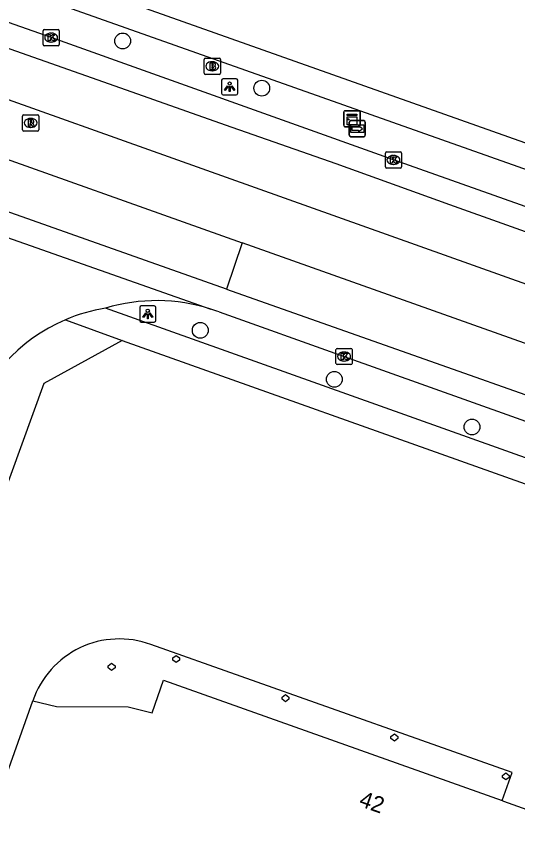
# Model space of a CAD drawing. Extents: x 155018 to 156648, y 383980 to 385733.
# Drawn here: x 155544.9 to 155575.9, y 385170.3 to 385221.4 of the extents above; entities that cross this region are included whole.
import ezdxf

# ---------------------------------------------------------------- set-up
doc = ezdxf.new("R2010")
doc.units = 0
for name, color, linetype in [('IMGEO_Boom', 7, 'Continuous'), ('IMGEO_Brandkraan', 7, 'Continuous'), ('IMGEO_Kast', 7, 'Continuous'), ('IMGEO_Kolk', 7, 'Continuous'), ('IMGEO_Lichtpunt', 7, 'Continuous'), ('IMGEO_OVBaan_gesloten', 7, 'Continuous'), ('IMGEO_Pand', 7, 'Continuous'), ('IMGEO_Pand_nummerreeks', 7, 'Continuous'), ('IMGEO_Pand_overbouw', 7, 'Continuous'), ('IMGEO_Rijbaan_lokaal_gesloten', 7, 'Continuous'), ('IMGEO_Rioolput', 7, 'Continuous'), ('IMGEO_Voetpad_open', 7, 'Continuous'), ('IMGEO_Wegwijzer', 7, 'Continuous')]:
    doc.layers.add(name, color=color, linetype=linetype)

msp = doc.modelspace()

# ---------------------------------------------------------------- linework, layer by layer
at = {"layer": 'IMGEO_Boom'}
for centre in [(155551.473, 385219.923), (155560.071, 385217.001), (155556.269, 385202.025), (155564.56, 385198.995), (155573.068, 385196.044)]:
    msp.add_circle(centre, 0.489, dxfattribs=at)
at = {"layer": 'IMGEO_Brandkraan'}
for p, q in [((155556.512, 385217.93), (155556.512, 385218.782)), ((155556.587, 385218.856), (155557.439, 385218.856)), ((155557.513, 385218.782), (155557.513, 385217.93)), ((155557, 385218.636), (155557.025, 385218.636)), ((155557.439, 385217.856), (155556.587, 385217.856)), ((155557.023, 385218.076), (155556.998, 385218.076))]:
    msp.add_line(p, q, dxfattribs=at)
for points in [[(155556.512, 385217.93), (155556.512, 385218.782)], [(155556.587, 385218.856), (155557.439, 385218.856)], [(155557.513, 385218.782), (155557.513, 385217.93)], [(155556.86, 385218.556), (155556.86, 385218.156), (155557.073, 385218.156)], [(155557.091, 385218.556), (155556.86, 385218.556)], [(155557.039, 385218.475), (155556.985, 385218.475), (155556.985, 385218.399)], [(155556.985, 385218.399), (155557.038, 385218.399)], [(155557.047, 385218.323), (155556.985, 385218.323), (155556.985, 385218.242)], [(155556.985, 385218.242), (155557.047, 385218.242)], [(155557.439, 385217.856), (155556.587, 385217.856)]]:
    msp.add_lwpolyline(points, dxfattribs=at)
for centre, radius, start, end in [((155556.589, 385218.78), 0.0765, 91.552, 178.448), ((155556.589, 385218.78), 0.0765, 91.552, 178.448), ((155557.437, 385218.78), 0.0765, 1.552, 88.448), ((155557.437, 385218.78), 0.0765, 1.552, 88.448), ((155557.04, 385218.437), 0.0379, 267.8285, 90.9355), ((155557.048, 385218.282), 0.0404, 269.8759, 90.5077), ((155557.095, 385218.411), 0.145, 59.4692, 91.5367), ((155557.12, 385218.458), 0.0922, 285.5137, 58.1501), ((155557.125, 385218.266), 0.105, 301.3115, 78.989), ((155556.589, 385217.932), 0.0765, 181.552, 268.448), ((155556.589, 385217.932), 0.0765, 181.552, 268.448), ((155557.079, 385218.407), 0.251, 268.6676, 293.5347), ((155557.437, 385217.932), 0.0765, 271.552, 358.448), ((155557.437, 385217.932), 0.0765, 271.552, 358.448)]:
    msp.add_arc(centre, radius, start, end, dxfattribs=at)
for centre, major_axis, ratio, start_param, end_param in [((155556.999, 385218.356), (-0.387, 0.002), 0.722429, 4.712389, 7.853982), ((155557.024, 385218.356), (-0.39, 0.002), 0.717154, 1.570796, 4.712389)]:
    msp.add_ellipse(centre, major_axis=major_axis, ratio=ratio, start_param=start_param, end_param=end_param, dxfattribs=at)
at = {"layer": 'IMGEO_Kast'}
for p, q in [((155565.149, 385214.682), (155565.149, 385215.523)), ((155565.149, 385215.523), (155565.149, 385214.682)), ((155565.224, 385215.607), (155566.065, 385215.607)), ((155566.065, 385215.607), (155565.224, 385215.607)), ((155566.149, 385215.532), (155566.149, 385214.691)), ((155566.149, 385214.691), (155566.149, 385215.532)), ((155566.074, 385214.607), (155565.233, 385214.607)), ((155565.233, 385214.607), (155566.074, 385214.607))]:
    msp.add_line(p, q, dxfattribs=at)
for points in [[(155565.344, 385215.397), (155565.944, 385215.397), (155565.944, 385215.312), (155565.344, 385215.312), (155565.344, 385215.397)], [(155565.344, 385215.222), (155565.944, 385215.222), (155565.944, 385214.733), (155565.344, 385214.733), (155565.344, 385215.222)]]:
    msp.add_lwpolyline(points, dxfattribs=at)
msp.add_circle((155565.428, 385215.071), 0.0377, dxfattribs=at)
for centre, start, end in [((155565.227, 385215.529), 92.4484, 184.2845), ((155565.227, 385215.529), 92.4484, 184.2845), ((155566.071, 385215.529), 2.4484, 94.2845), ((155566.071, 385215.529), 2.4484, 94.2845), ((155565.227, 385214.685), 182.4484, 274.2845), ((155565.227, 385214.685), 182.4484, 274.2845), ((155566.071, 385214.685), 272.4484, 4.2845), ((155566.071, 385214.685), 272.4484, 4.2845)]:
    msp.add_arc(centre, 0.0779, start, end, dxfattribs=at)
at = {"layer": 'IMGEO_Kolk'}
for p, q in [((155546.551, 385219.702), (155546.551, 385220.554)), ((155546.626, 385220.628), (155547.478, 385220.628)), ((155547.039, 385220.408), (155547.064, 385220.408)), ((155547.552, 385220.554), (155547.552, 385219.702)), ((155547.062, 385219.848), (155547.037, 385219.848)), ((155547.478, 385219.628), (155546.626, 385219.628)), ((155567.713, 385212.135), (155567.713, 385212.987)), ((155567.788, 385213.061), (155568.64, 385213.061)), ((155568.201, 385212.841), (155568.226, 385212.841)), ((155568.714, 385212.987), (155568.714, 385212.135)), ((155568.224, 385212.281), (155568.199, 385212.281)), ((155568.64, 385212.061), (155567.788, 385212.061)), ((155564.661, 385199.976), (155564.661, 385200.828)), ((155564.736, 385200.902), (155565.588, 385200.902)), ((155565.662, 385200.828), (155565.662, 385199.976)), ((155565.149, 385200.682), (155565.174, 385200.682)), ((155565.588, 385199.902), (155564.736, 385199.902)), ((155565.172, 385200.122), (155565.147, 385200.122))]:
    msp.add_line(p, q, dxfattribs=at)
for points in [[(155546.551, 385219.702), (155546.551, 385220.554)], [(155546.626, 385220.628), (155547.478, 385220.628)], [(155546.872, 385220.328), (155546.995, 385220.328), (155546.995, 385220.177), (155547.125, 385220.328), (155547.289, 385220.328), (155547.143, 385220.177), (155547.296, 385219.928), (155547.144, 385219.928), (155547.059, 385220.092), (155546.995, 385220.025), (155546.995, 385219.928), (155546.872, 385219.928), (155546.872, 385220.328)], [(155547.552, 385220.554), (155547.552, 385219.702)], [(155547.478, 385219.628), (155546.626, 385219.628)], [(155567.713, 385212.135), (155567.713, 385212.987)], [(155567.788, 385213.061), (155568.64, 385213.061)], [(155568.034, 385212.761), (155568.157, 385212.761), (155568.157, 385212.61), (155568.287, 385212.761), (155568.451, 385212.761), (155568.305, 385212.61), (155568.458, 385212.361), (155568.306, 385212.361), (155568.221, 385212.525), (155568.157, 385212.458), (155568.157, 385212.361), (155568.034, 385212.361), (155568.034, 385212.761)], [(155568.714, 385212.987), (155568.714, 385212.135)], [(155568.64, 385212.061), (155567.788, 385212.061)], [(155564.661, 385199.976), (155564.661, 385200.828)], [(155564.736, 385200.902), (155565.588, 385200.902)], [(155565.662, 385200.828), (155565.662, 385199.976)], [(155564.982, 385200.602), (155565.105, 385200.602), (155565.105, 385200.451), (155565.235, 385200.602), (155565.399, 385200.602), (155565.253, 385200.451), (155565.406, 385200.202), (155565.254, 385200.202), (155565.169, 385200.366), (155565.105, 385200.299), (155565.105, 385200.202), (155564.982, 385200.202), (155564.982, 385200.602)], [(155565.588, 385199.902), (155564.736, 385199.902)]]:
    msp.add_lwpolyline(points, dxfattribs=at)
for centre, start, end in [((155546.628, 385220.552), 91.552, 178.448), ((155546.628, 385220.552), 91.552, 178.448), ((155547.476, 385220.552), 1.552, 88.448), ((155547.476, 385220.552), 1.552, 88.448), ((155546.628, 385219.704), 181.552, 268.448), ((155546.628, 385219.704), 181.552, 268.448), ((155547.476, 385219.704), 271.552, 358.448), ((155547.476, 385219.704), 271.552, 358.448), ((155567.79, 385212.985), 91.552, 178.448), ((155567.79, 385212.985), 91.552, 178.448), ((155568.638, 385212.985), 1.552, 88.448), ((155568.638, 385212.985), 1.552, 88.448), ((155567.79, 385212.137), 181.552, 268.448), ((155567.79, 385212.137), 181.552, 268.448), ((155568.638, 385212.137), 271.552, 358.448), ((155568.638, 385212.137), 271.552, 358.448), ((155564.738, 385200.826), 91.552, 178.448), ((155564.738, 385200.826), 91.552, 178.448), ((155565.586, 385200.826), 1.552, 88.448), ((155565.586, 385200.826), 1.552, 88.448), ((155564.738, 385199.978), 181.552, 268.448), ((155564.738, 385199.978), 181.552, 268.448), ((155565.586, 385199.978), 271.552, 358.448), ((155565.586, 385199.978), 271.552, 358.448)]:
    msp.add_arc(centre, 0.0765, start, end, dxfattribs=at)
for centre, major_axis, ratio, start_param, end_param in [((155547.038, 385220.128), (-0.387, 0.002), 0.722429, 4.712389, 7.853982), ((155547.063, 385220.128), (-0.39, 0.002), 0.717154, 1.570796, 4.712389), ((155568.2, 385212.561), (-0.387, 0.002), 0.722429, 4.712389, 7.853982), ((155568.225, 385212.561), (-0.39, 0.002), 0.717154, 1.570796, 4.712389), ((155565.148, 385200.402), (-0.387, 0.002), 0.722429, 4.712389, 7.853982), ((155565.173, 385200.402), (-0.39, 0.002), 0.717154, 1.570796, 4.712389)]:
    msp.add_ellipse(centre, major_axis=major_axis, ratio=ratio, start_param=start_param, end_param=end_param, dxfattribs=at)
at = {"layer": 'IMGEO_Lichtpunt'}
for p, q in [((155557.588, 385217.491), (155557.588, 385216.684)), ((155557.588, 385217.491), (155557.588, 385216.684)), ((155558.49, 385217.586), (155557.682, 385217.586)), ((155558.49, 385217.586), (155557.682, 385217.586)), ((155558.584, 385216.684), (155558.584, 385217.491)), ((155558.584, 385216.684), (155558.584, 385217.491)), ((155557.682, 385216.59), (155558.49, 385216.59)), ((155557.682, 385216.59), (155558.49, 385216.59)), ((155552.525, 385203.435), (155552.525, 385202.628)), ((155552.525, 385203.435), (155552.525, 385202.628)), ((155553.427, 385203.53), (155552.619, 385203.53)), ((155553.427, 385203.53), (155552.619, 385203.53)), ((155553.521, 385202.628), (155553.521, 385203.435)), ((155553.521, 385202.628), (155553.521, 385203.435)), ((155552.619, 385202.534), (155553.427, 385202.534)), ((155552.619, 385202.534), (155553.427, 385202.534))]:
    msp.add_line(p, q, dxfattribs=at)
for points in [[(155557.962, 385217.155), (155558.001, 385217.127), (155557.813, 385216.865), (155557.775, 385216.892), (155557.962, 385217.155)], [(155558.064, 385217.107), (155558.111, 385217.107), (155558.111, 385216.785), (155558.064, 385216.785), (155558.064, 385217.107)], [(155558.174, 385217.127), (155558.212, 385217.154), (155558.399, 385216.892), (155558.36, 385216.864), (155558.174, 385217.127)], [(155552.899, 385203.099), (155552.938, 385203.071), (155552.75, 385202.809), (155552.712, 385202.836), (155552.899, 385203.099)], [(155553.001, 385203.051), (155553.048, 385203.051), (155553.048, 385202.729), (155553.001, 385202.729), (155553.001, 385203.051)], [(155553.111, 385203.071), (155553.149, 385203.098), (155553.336, 385202.836), (155553.297, 385202.808), (155553.111, 385203.071)]]:
    msp.add_lwpolyline(points, dxfattribs=at)
for centre in [(155558.087, 385217.289), (155553.024, 385203.233)]:
    msp.add_circle(centre, 0.0994, dxfattribs=at)
for centre, start, end in [((155557.682, 385217.491), 90, 180), ((155557.682, 385217.491), 90, 180), ((155558.49, 385217.491), 0, 90), ((155558.49, 385217.491), 0, 90), ((155557.682, 385216.684), 180, 270), ((155557.682, 385216.684), 180, 270), ((155558.49, 385216.684), 270, 0), ((155558.49, 385216.684), 270, 360), ((155552.619, 385203.435), 90, 180), ((155552.619, 385203.435), 90, 180), ((155553.427, 385203.435), 0, 90), ((155553.427, 385203.435), 0, 90), ((155552.619, 385202.628), 180, 270), ((155552.619, 385202.628), 180, 270), ((155553.427, 385202.628), 270, 0), ((155553.427, 385202.628), 270, 360)]:
    msp.add_arc(centre, 0.0946, start, end, dxfattribs=at)
at = {"layer": 'IMGEO_OVBaan_gesloten'}
for points in [[(155513.143, 385227.411), (155532.678, 385220.473), (155596.803, 385197.629), (155623.968, 385187.963)], [(155511.979, 385224.068), (155531.528, 385217.123), (155540.881, 385213.823), (155558.855, 385207.433)], [(155622.855, 385184.672), (155594.693, 385194.693), (155558.855, 385207.433)]]:
    msp.add_lwpolyline(points, dxfattribs=at)
at = {"layer": 'IMGEO_Pand'}
for points in [[(155550.791, 385180.993), (155550.582, 385181.145), (155550.582, 385181.281), (155550.791, 385181.433), (155551, 385181.281), (155551, 385181.145), (155550.791, 385180.993)], [(155554.782, 385181.473), (155554.573, 385181.625), (155554.573, 385181.761), (155554.782, 385181.913), (155554.991, 385181.761), (155554.991, 385181.625), (155554.782, 385181.473)], [(155564.352, 385122.443), (155569.181, 385136.025), (155534.942, 385148.201), (155545.918, 385179.107), (155547.38, 385178.749), (155551.81, 385178.73), (155553.29, 385178.36), (155554, 385180.39), (155574.93, 385172.934), (155575.009, 385172.906), (155581.819, 385170.48), (155577.589, 385158.606), (155588.821, 385154.605), (155575.936, 385118.324), (155564.352, 385122.443)], [(155561.537, 385179.054), (155561.328, 385179.206), (155561.328, 385179.342), (155561.537, 385179.494), (155561.746, 385179.342), (155561.746, 385179.206), (155561.537, 385179.054)], [(155568.269, 385176.623), (155568.06, 385176.775), (155568.06, 385176.911), (155568.269, 385177.063), (155568.478, 385176.911), (155568.478, 385176.775), (155568.269, 385176.623)], [(155575.163, 385174.212), (155574.954, 385174.364), (155574.954, 385174.5), (155575.163, 385174.652), (155575.372, 385174.5), (155575.372, 385174.364), (155575.163, 385174.212)]]:
    msp.add_lwpolyline(points, dxfattribs=at)
at = {"layer": 'IMGEO_Pand_overbouw'}
msp.add_lwpolyline([(155545.918, 385179.107), (155547.38, 385178.749), (155551.81, 385178.73), (155553.29, 385178.36), (155554, 385180.39), (155574.93, 385172.934), (155575.546, 385174.673), (155553.217, 385182.592)], dxfattribs=at)
msp.add_arc((155551.271, 385177.282), 5.656, 69.8752, 161.1702, dxfattribs=at)
at = {"layer": 'IMGEO_Rijbaan_lokaal_gesloten'}
for points in [[(155557.9, 385204.567), (155537.191, 385211.882), (155513.737, 385220.252), (155503.557, 385224.201), (155495.838, 385228.015), (155486.554, 385233.732), (155475.915, 385241.101)], [(155645.511, 385185.075), (155642.46, 385186.17), (155625.397, 385192.189), (155624.083, 385192.653), (155605.809, 385199.206), (155586.53, 385206.07), (155568.213, 385212.56), (155547.052, 385220.126), (155528.7, 385226.617), (155515.285, 385231.385), (155509.453, 385233.651), (155508.191, 385234.171)], [(155665.693, 385176.263), (155660.553, 385178.023), (155655.607, 385179.77), (155650.865, 385181.503), (155646.123, 385183.237), (155641.251, 385185.008), (155635.549, 385187.017), (155629.846, 385189.027), (155624.143, 385191.036), (155614.94, 385194.316), (155604.772, 385197.946), (155594.604, 385201.576), (155585.786, 385204.731), (155578.741, 385207.262), (155571.696, 385209.794), (155564.668, 385212.315), (155557.835, 385214.719), (155551.002, 385217.123), (155544.169, 385219.528)], [(155529.532, 385212.984), (155556.922, 385203.342)], [(155558.855, 385207.433), (155557.9, 385204.567)], [(155557.9, 385204.567), (155590.359, 385193.1), (155633.902, 385177.519), (155691.943, 385156.871), (155720.534, 385146.692), (155727.048, 385144.078), (155745.946, 385136.269), (155751.443, 385134.141), (155754.812, 385131.974), (155774.682, 385119.558)], [(155557.428, 385203.169), (155565.162, 385200.403), (155583.484, 385193.878), (155588.963, 385191.911)]]:
    msp.add_lwpolyline(points, dxfattribs=at)
for centre, radius, start, end in [((155552.199, 385192.715), 10.834, 99.4856, 113.1733), ((155553.571, 385192.743), 11.116, 72.4551, 106.5063), ((155553.995, 385193.953), 9.835, 69.5667, 72.6825), ((155552.192, 385192.723), 10.824, 113.1578, 162.4783)]:
    msp.add_arc(centre, radius, start, end, dxfattribs=at)
at = {"layer": 'IMGEO_Rioolput'}
for p, q in [((155545.285, 385214.425), (155545.285, 385215.277)), ((155545.36, 385215.351), (155546.212, 385215.351)), ((155545.773, 385215.131), (155545.798, 385215.131)), ((155546.286, 385215.277), (155546.286, 385214.425)), ((155546.212, 385214.351), (155545.36, 385214.351)), ((155545.796, 385214.571), (155545.771, 385214.571))]:
    msp.add_line(p, q, dxfattribs=at)
for points in [[(155545.285, 385214.425), (155545.285, 385215.277)], [(155545.36, 385215.351), (155546.212, 385215.351)], [(155546.286, 385215.277), (155546.286, 385214.425)], [(155545.874, 385215.049), (155545.622, 385215.051), (155545.622, 385214.651)], [(155545.622, 385214.651), (155545.746, 385214.651), (155545.746, 385214.813), (155545.757, 385214.813)], [(155545.8, 385214.97), (155545.746, 385214.97), (155545.746, 385214.889)], [(155545.746, 385214.889), (155545.798, 385214.889)], [(155545.804, 385214.784), (155545.875, 385214.651), (155546.015, 385214.651), (155545.95, 385214.777)], [(155546.212, 385214.351), (155545.36, 385214.351)]]:
    msp.add_lwpolyline(points, dxfattribs=at)
for centre, radius, start, end in [((155545.362, 385215.275), 0.0765, 91.552, 178.448), ((155545.362, 385215.275), 0.0765, 91.552, 178.448), ((155546.21, 385215.275), 0.0765, 1.552, 88.448), ((155546.21, 385215.275), 0.0765, 1.552, 88.448), ((155545.756, 385214.76), 0.0533, 26.0293, 88.6989), ((155545.782, 385215.078), 0.19, 274.7715, 282.9687), ((155545.806, 385214.874), 0.0964, 77.0061, 93.1865), ((155545.82, 385214.931), 0.0378, 276.6634, 79.6772), ((155545.873, 385214.939), 0.109, 350.3612, 89.416), ((155545.871, 385214.939), 0.112, 277.5842, 350.9817), ((155545.855, 385214.724), 0.108, 29.5134, 73.7905), ((155545.362, 385214.427), 0.0765, 181.552, 268.448), ((155545.362, 385214.427), 0.0765, 181.552, 268.448), ((155546.21, 385214.427), 0.0765, 271.552, 358.448), ((155546.21, 385214.427), 0.0765, 271.552, 358.448)]:
    msp.add_arc(centre, radius, start, end, dxfattribs=at)
for centre, major_axis, ratio, start_param, end_param in [((155545.772, 385214.851), (-0.387, 0.002), 0.722429, 4.712389, 7.853982), ((155545.797, 385214.851), (-0.39, 0.002), 0.717154, 1.570796, 4.712389)]:
    msp.add_ellipse(centre, major_axis=major_axis, ratio=ratio, start_param=start_param, end_param=end_param, dxfattribs=at)
at = {"layer": 'IMGEO_Voetpad_open'}
for points in [[(155650.233, 385187.375), (155585.597, 385210.337), (155509.618, 385237.262), (155501.834, 385241.047), (155500, 385242.323), (155488.965, 385250), (155486.638, 385251.619), (155445.26, 385280.65), (155445.254, 385280.803)], [(155508.89, 385235.892), (155584.981, 385208.934), (155652.019, 385185.08)], [(155588.282, 385189.891), (155550.413, 385203.401)], [(155547.935, 385202.675), (155551.448, 385201.401)], [(155551.448, 385201.401), (155546.604, 385198.733), (155542.42, 385187.249), (155529.708, 385151.464)], [(155551.448, 385201.401), (155601.269, 385183.671), (155602.298, 385183.305), (155620.236, 385176.93), (155661.245, 385162.355), (155670.014, 385159.249), (155717.596, 385142.395), (155751.396, 385130.416)]]:
    msp.add_lwpolyline(points, dxfattribs=at)
at = {"layer": 'IMGEO_Wegwijzer'}
for p, q in [((155565.484, 385214.096), (155565.484, 385214.896)), ((155565.484, 385214.896), (155565.484, 385214.096)), ((155565.584, 385214.996), (155566.374, 385214.996)), ((155566.374, 385214.996), (155565.584, 385214.996)), ((155566.474, 385214.896), (155566.474, 385214.096)), ((155566.474, 385214.096), (155566.474, 385214.896)), ((155566.374, 385213.996), (155565.584, 385213.996)), ((155565.584, 385213.996), (155566.374, 385213.996))]:
    msp.add_line(p, q, dxfattribs=at)
for points in [[(155565.585, 385214.728), (155566.373, 385214.728), (155566.373, 385214.264), (155565.585, 385214.264), (155565.585, 385214.728)], [(155565.65, 385214.58), (155565.65, 385214.496), (155565.65, 385214.412), (155566.061, 385214.412), (155566.061, 385214.329), (155566.308, 385214.496), (155566.061, 385214.663), (155566.061, 385214.58), (155565.65, 385214.58)]]:
    msp.add_lwpolyline(points, dxfattribs=at)
for centre, start, end in [((155565.584, 385214.896), 90, 180), ((155565.584, 385214.896), 90, 180), ((155566.374, 385214.896), 0, 90), ((155566.374, 385214.896), 360, 90), ((155565.584, 385214.096), 180, 270), ((155565.584, 385214.096), 180, 270), ((155566.374, 385214.096), 270, 0), ((155566.374, 385214.096), 270, 0)]:
    msp.add_arc(centre, 0.1, start, end, dxfattribs=at)

# ---------------------------------------------------------------- texts
at = {"layer": 'IMGEO_Pand_nummerreeks'}
msp.add_text('42', height=1, rotation=340.3934, dxfattribs=at).set_placement((155566.027, 385172.623))

doc.saveas('drawing.dxf')
